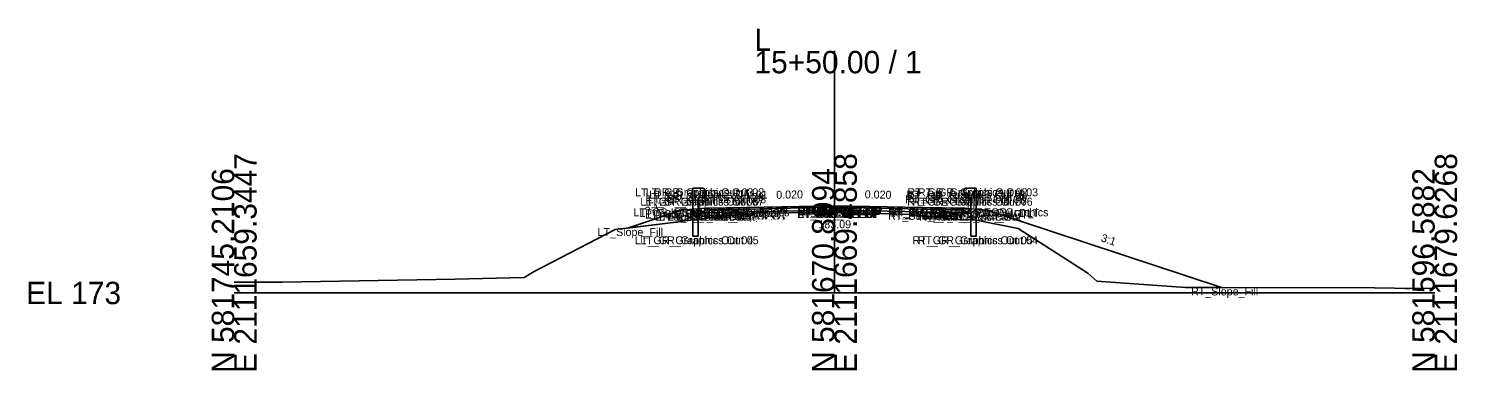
# Model space of a CAD drawing. Extents: x -486 to 1153, y -333 to 9539.
# Drawn here: x -25.7 to 152.8, y 5990.3 to 6033.1 of the extents above; entities that cross this region are included whole.
import ezdxf

# ---------------------------------------------------------------- set-up
doc = ezdxf.new("R2010")
doc.units = 0
for name, color, linetype in [('Default', 7, 'Continuous'), ('Exist Cross Section Cell', 7, 'Continuous'), ('Exist XS Ground Line', 7, 'Continuous'), ('Prop CMT Guardrail Graphics', 7, 'Continuous'), ('Prop CMT Pvmt Course 1', 7, 'Continuous'), ('Prop CMT Pvmt Course 2', 7, 'Continuous'), ('Prop CMT Pvmt Course 3', 7, 'Continuous'), ('Prop CMT Pvmt Surface', 7, 'Continuous'), ('Prop CMT Pvmt Surface Shoulder', 7, 'Continuous'), ('Prop CMT Shld Paved Course 1', 7, 'Continuous'), ('Prop CMT Shld Paved Course 2', 7, 'Continuous'), ('Prop CMT Shld Paved Course 3', 7, 'Continuous'), ('Prop CMT Slope Grass', 7, 'Continuous'), ('Prop CMT Subgrade Earthwork', 7, 'Continuous'), ('Prop XS Earthwork Shape', 7, 'Continuous'), ('Prop XS SE Text', 7, 'Continuous'), ('Prop XS Side Slope Text', 7, 'Continuous'), ('Scratch_Level_0', 7, 'Continuous')]:
    doc.layers.add(name, color=color, linetype=linetype)

msp = doc.modelspace()

# ---------------------------------------------------------------- linework, layer by layer
at = {"layer": 'Exist Cross Section Cell'}
for p, q in [((75, 6000), (75, 6030.27)), ((0, 6000), (75, 6000)), ((75, 6000), (150, 6000))]:
    msp.add_line(p, q, dxfattribs=at)
at = {"layer": 'Exist XS Ground Line'}
for p, q in [((57.93, 6009.23), (65.25, 6009.99)), ((65.25, 6009.99), (73.4, 6010.07)), ((73.4, 6010.07), (74.83, 6010.09)), ((74.83, 6010.09), (83.25, 6009.87)), ((83.25, 6009.87), (84.67, 6009.83)), ((84.67, 6009.83), (90.41, 6009.2)), ((37.49, 6002.67), (47.6, 6007.93)), ((47.6, 6007.93), (54.83, 6008.81)), ((54.83, 6008.81), (57.93, 6009.23)), ((90.41, 6009.2), (92.5, 6009.13)), ((92.5, 6009.13), (97.95, 6008.08)), ((97.95, 6008.08), (106.66, 6002.47)), ((36.24, 6001.94), (37.49, 6002.67)), ((106.66, 6002.47), (107.79, 6001.47)), ((0, 6001.36), (3.26, 6001.37)), ((3.26, 6001.37), (5.98, 6001.35)), ((5.98, 6001.35), (27.59, 6001.71)), ((27.59, 6001.71), (36.24, 6001.94)), ((107.79, 6001.47), (118.87, 6000.69)), ((118.87, 6000.69), (142.48, 6000.65)), ((142.48, 6000.65), (144.99, 6000.58)), ((144.99, 6000.58), (146.31, 6000.57)), ((146.31, 6000.57), (146.96, 6000.56)), ((146.96, 6000.56), (150, 6000.58))]:
    msp.add_line(p, q, dxfattribs=at)
at = {"layer": 'Prop CMT Guardrail Graphics'}
for points in [[(57.3, 6007.09), (57.3, 6013.09)], [(57.3, 6013.09), (58.63, 6013.09), (58.9, 6012.79)], [(92.7, 6013.09), (91.37, 6013.09), (91.1, 6012.79)], [(92.7, 6007.09), (92.7, 6013.09)], [(58.9, 6012.21), (58.63, 6011.92), (57.96, 6011.92)], [(57.96, 6011.92), (57.96, 6007.09)], [(58.9, 6012.79), (58.63, 6012.5)], [(58.63, 6012.5), (58.9, 6012.21)], [(91.1, 6012.79), (91.37, 6012.5)], [(91.37, 6012.5), (91.1, 6012.21)], [(91.1, 6012.21), (91.37, 6011.92), (92.04, 6011.92)], [(92.04, 6011.92), (92.04, 6007.09)], [(57.96, 6007.09), (57.3, 6007.09)], [(92.04, 6007.09), (92.7, 6007.09)]]:
    msp.add_lwpolyline(points, dxfattribs=at)
at = {"layer": 'Prop CMT Pvmt Course 1'}
for points in [[(75, 6010.91), (64, 6010.69)], [(64, 6010.49), (75, 6010.71)], [(64, 6010.69), (64, 6010.49)], [(75, 6010.71), (75, 6010.91)], [(75, 6010.91), (86, 6010.69)], [(75, 6010.71), (75, 6010.91)], [(86, 6010.49), (75, 6010.71)], [(86, 6010.69), (86, 6010.49)]]:
    msp.add_lwpolyline(points, dxfattribs=at)
msp.add_lwpolyline([(75, 6010.71), (75, 6010.79), (75, 6010.79), (75, 6010.71)], close=True, dxfattribs=at)
msp.add_lwpolyline([(75, 6010.71), (75, 6010.79), (75, 6010.79), (75, 6010.71)], close=True, dxfattribs=at)
at = {"layer": 'Prop CMT Pvmt Course 2'}
for points in [[(75, 6010.71), (64, 6010.49)], [(64, 6010.49), (64, 6010.15)], [(64, 6010.15), (75, 6010.37)], [(75, 6010.37), (75, 6010.71)], [(75, 6010.37), (75, 6010.71)], [(75, 6010.71), (86, 6010.49)], [(86, 6010.15), (75, 6010.37)], [(86, 6010.49), (86, 6010.15)]]:
    msp.add_lwpolyline(points, dxfattribs=at)
at = {"layer": 'Prop CMT Pvmt Course 3'}
for points in [[(75, 6010.37), (64, 6010.15)], [(64, 6010.15), (64, 6010.15)], [(75, 6010.37), (75, 6010.37)], [(75, 6010.37), (86, 6010.15)], [(75, 6010.37), (75, 6010.37)], [(86, 6010.15), (86, 6010.15)]]:
    msp.add_lwpolyline(points, dxfattribs=at)
at = {"layer": 'Prop CMT Pvmt Surface'}
for points in [[(75, 6010.91), (64, 6010.69)], [(75, 6010.91), (86, 6010.69)]]:
    msp.add_lwpolyline(points, dxfattribs=at)
at = {"layer": 'Prop CMT Pvmt Surface Shoulder'}
for points in [[(64, 6010.69), (59, 6010.59)], [(86, 6010.69), (91, 6010.59)]]:
    msp.add_lwpolyline(points, dxfattribs=at)
at = {"layer": 'Prop CMT Shld Paved Course 1'}
for points in [[(64, 6010.69), (59, 6010.59), (58.79, 6010.38)], [(58.79, 6010.38), (64, 6010.49)], [(64, 6010.49), (64, 6010.69)], [(86, 6010.69), (91, 6010.59), (91.21, 6010.38)], [(86, 6010.49), (86, 6010.69)], [(91.21, 6010.38), (86, 6010.49)]]:
    msp.add_lwpolyline(points, dxfattribs=at)
at = {"layer": 'Prop CMT Shld Paved Course 2'}
for points in [[(64, 6010.49), (58.79, 6010.38), (58.45, 6010.04)], [(58.45, 6010.04), (64, 6010.15)], [(64, 6010.15), (64, 6010.49)], [(86, 6010.49), (91.21, 6010.38), (91.55, 6010.04)], [(86, 6010.15), (86, 6010.49)], [(91.55, 6010.04), (86, 6010.15)]]:
    msp.add_lwpolyline(points, dxfattribs=at)
at = {"layer": 'Prop CMT Shld Paved Course 3'}
for points in [[(64, 6010.15), (58.45, 6010.04)], [(58.45, 6010.04), (58.45, 6010.04), (58.45, 6010.04)], [(64, 6010.15), (64, 6010.15)], [(86, 6010.15), (91.55, 6010.04)], [(86, 6010.15), (86, 6010.15)], [(91.55, 6010.04), (91.55, 6010.04), (91.55, 6010.04)]]:
    msp.add_lwpolyline(points, dxfattribs=at)
at = {"layer": 'Prop CMT Slope Grass'}
for points in [[(55.9, 6010.35), (49.16, 6008.12)], [(58.9, 6010.59), (55.9, 6010.35)], [(59, 6010.59), (58.9, 6010.59)], [(91, 6010.59), (91.1, 6010.59)], [(91.1, 6010.59), (94.1, 6010.35)], [(94.1, 6010.35), (123.37, 6000.69)]]:
    msp.add_lwpolyline(points, dxfattribs=at)
at = {"layer": 'Prop CMT Subgrade Earthwork'}
for points in [[(58.45, 6010.04), (57.98, 6010.51)], [(64, 6010.15), (58.45, 6010.04)], [(75, 6010.37), (64, 6010.15)], [(75, 6010.37), (86, 6010.15)], [(86, 6010.15), (91.55, 6010.04)], [(91.55, 6010.04), (92.02, 6010.51)]]:
    msp.add_lwpolyline(points, dxfattribs=at)
at = {"layer": 'Prop XS Earthwork Shape'}
msp.add_lwpolyline([(65.25, 6009.99), (73.4, 6010.07), (74.83, 6010.09), (83.25, 6009.87), (84.67, 6009.83), (90.41, 6009.2), (92.5, 6009.13), (97.95, 6008.08), (106.66, 6002.47), (107.79, 6001.47), (118.87, 6000.69), (123.37, 6000.69), (94.1, 6010.35), (92.02, 6010.51), (91.55, 6010.04), (86, 6010.15), (75, 6010.37), (64, 6010.15), (58.45, 6010.04), (57.98, 6010.51), (55.9, 6010.35), (49.16, 6008.12), (54.83, 6008.81), (57.93, 6009.23)], close=True, dxfattribs=at)

# ---------------------------------------------------------------- texts
at = {"layer": 'Default'}
for s, height, p in [('183.09', 1, (72.99, 6008.09)), ('-', 0.0001, (0, 6000))]:
    msp.add_text(s, height=height, dxfattribs=at).set_placement(p)
at = {"layer": 'Exist Cross Section Cell'}
for s, p in [('L', (65, 6030.27)), ('15+50.00 / 1', (65, 6027.47)), ('EL 173', (-26, 5998.6))]:
    msp.add_text(s, height=2.8, dxfattribs=at).set_placement(p)
for s, p in [('E 2111659.3447', (2.8, 5990)), ('E 2111669.4858', (77.8, 5990)), ('E 2111679.6268', (152.8, 5990)), ('N 581745.2106', (0, 5990)), ('N 581670.8994', (75, 5990)), ('N 581596.5882', (150, 5990))]:
    msp.add_text(s, height=2.8, rotation=90, dxfattribs=at).set_placement(p)
at = {"layer": 'Prop XS SE Text'}
for rotation, p in [(1.1458, (67.73, 6011.77)), (358.8542, (78.77, 6011.84))]:
    msp.add_text('0.020', height=1, rotation=rotation, dxfattribs=at).set_placement(p)
at = {"layer": 'Prop XS Side Slope Text'}
for rotation, p in [(18.2629, (51.54, 6009.7)), (341.7371, (108.22, 6006.48))]:
    msp.add_text('3:1', height=1, rotation=rotation, dxfattribs=at).set_placement(p)
at = {"layer": 'Scratch_Level_0'}
for s, p in [('LT_GR_Graphics Out 03', (50.08, 6012.09)), ('LT_GR_Graphics Out 02', (51.43, 6012.09)), ('RT_GR_Graphics Out 02', (84.11, 6012.09)), ('RT_GR_Graphics Out 03', (85.43, 6012.09)), ('LT_GR_Graphics Out 06', (50.74, 6010.92)), ('LT_GR_Graphics Out 07', (51.39, 6010.92)), ('LT_GR_Graphics Out 09', (51.4, 6011.5)), ('LT_GR_Graphics Out 08', (51.67, 6011.21)), ('LT_GR_Graphics Out 01', (51.85, 6011.79)), ('RT_GR_Graphics Out 08', (83.81, 6011.21)), ('RT_GR_Graphics Out 01', (83.99, 6011.79)), ('RT_GR_Graphics Out 07', (84.07, 6010.92)), ('RT_GR_Graphics Out 09', (84.09, 6011.5)), ('RT_GR_Graphics Out 06', (84.75, 6010.92)), ('LT_GS_OS_GR_Face_Graphics', (49.9, 6009.59)), ('LT_Sub_Trench_Out_DLT', (50.63, 6009.51)), ('LT_GS_OS_CTL', (51.36, 6009.35)), ('LT_Sub_Trench_Out', (52.56, 6009.04)), ('LT_PS3_Shelf_Out', (53.1, 6009.04)), ('LT_PS3_OEOP', (54.23, 6009.04)), ('LT_PS2_OEOP', (54.57, 6009.38)), ('LT_PS1_OEOP', (54.91, 6009.59)), ('LT_PV2_OEOT', (59.75, 6009.49)), ('LT_PV3_OEOT', (59.75, 6009.15)), ('LT_Sub_OEOT', (59.77, 6009.15)), ('LT_PV1_OEOT', (59.87, 6009.69)), ('RT_PV2_OEEOP', (70.33, 6009.71)), ('RT_PV3_OEEOP', (70.33, 6009.37)), ('RT_Sub_OEEOP', (70.36, 6009.37)), ('LT_PV2_OEEOP', (70.39, 6009.71)), ('LT_PV3_OEEOP', (70.39, 6009.37)), ('LT_Sub_OEEOP', (70.42, 6009.37)), ('RT_PV1_OEEOP', (70.45, 6009.79)), ('LT_PV1_OEEOP', (70.51, 6009.79)), ('RT_PV2_IEEOP', (70.71, 6009.71)), ('LT_PV2_IEEOP', (70.77, 6009.71)), ('RT_PV1_IEEOP', (70.83, 6009.79)), ('LT_PV1_IEEOP', (70.89, 6009.79)), ('PV2_PGL', (72.35, 6009.71)), ('PV1_PGL', (72.47, 6009.91)), ('RT_PV2_OEOT', (81.69, 6009.49)), ('RT_PV3_OEOT', (81.69, 6009.15)), ('RT_Sub_OEOT', (81.71, 6009.15)), ('RT_PV1_OEOT', (81.81, 6009.69)), ('RT_GS_OS_GR_Face_Graphics', (82.04, 6009.59)), ('RT_Sub_Trench_Out_DLT', (84.61, 6009.51)), ('RT_Sub_Trench_Out', (85.6, 6009.04)), ('RT_PS3_Shelf_Out', (86.15, 6009.04)), ('RT_PS1_OEOP', (86.85, 6009.59)), ('RT_PS2_OEOP', (86.94, 6009.38)), ('RT_PS3_OEOP', (87.28, 6009.04)), ('RT_GS_OS_CTL', (89.5, 6009.35)), ('LT_Slope_Fill', (45.4, 6007.12)), ('LT_GR_Graphics Out 04', (50.07, 6006.09)), ('LT_GR_Graphics Out 05', (50.74, 6006.09)), ('RT_GR_Graphics Out 05', (84.76, 6006.09)), ('RT_GR_Graphics Out 04', (85.41, 6006.09)), ('RT_Slope_Fill', (119.55, 5999.69))]:
    msp.add_text(s, height=1, dxfattribs=at).set_placement(p)

doc.saveas('drawing.dxf')
